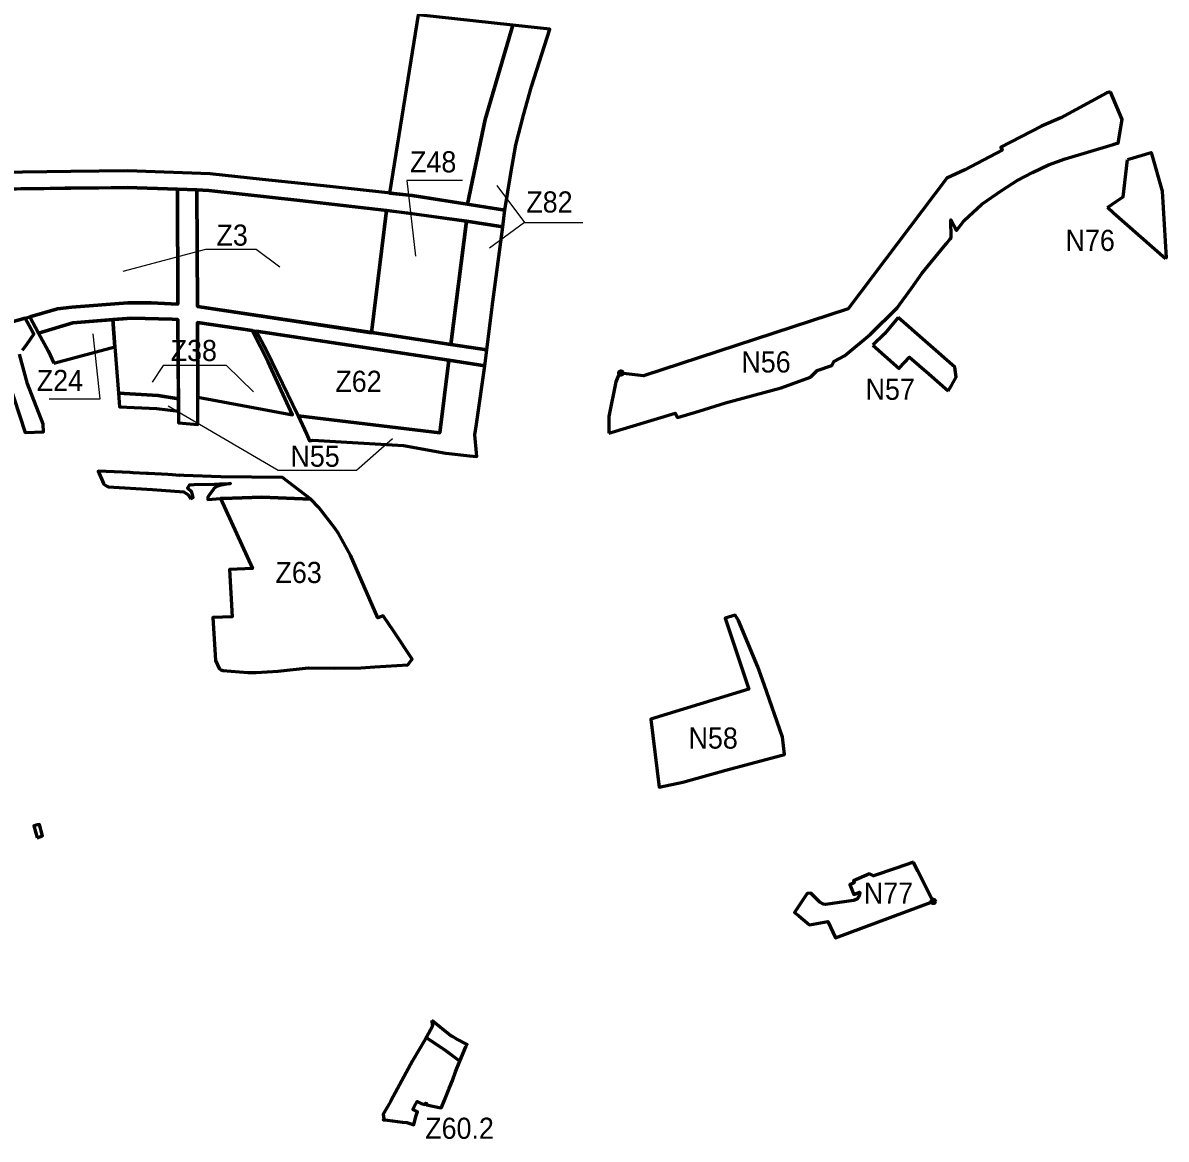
# Model space of a CAD drawing. Extents: x -650277 to -643420, y -1073980 to -1066720.
# Drawn here: x -647259 to -645961, y -1070629 to -1069362 of the extents above; entities that cross this region are included whole.
import ezdxf

# ---------------------------------------------------------------- set-up
doc = ezdxf.new("R2010")
doc.units = 0
doc.header["$LTSCALE"] = 9.6
doc.header["$PDMODE"] = 32
doc.header["$PDSIZE"] = 4.8
for name, color, linetype, lineweight in [('1', 7, 'Continuous', 60), ('13', 7, 'Continuous', 60), ('15', 7, 'Continuous', 60), ('18', 7, 'Continuous', 60), ('42', 7, 'Continuous', 60), ('48', 7, 'Continuous', 60), ('60', 7, 'Continuous', 60), ('63', 7, 'Continuous', 25), ('9', 7, 'Continuous', 60)]:
    doc.layers.add(name, color=color, linetype=linetype, lineweight=lineweight)

msp = doc.modelspace()

# ---------------------------------------------------------------- linework, layer by layer
at = {"layer": '1'}
for points in [[(-647251.002, -1069695.852), (-647219.628, -1069686.746), (-647203.374, -1069684.716), (-647139.649, -1069679.961), (-647113.255, -1069679.966), (-647082.761, -1069681.399), (-647083.356, -1069551.018), (-647140.247, -1069549.071), (-647158.572, -1069549.252), (-647211.05, -1069549.77), (-647227.623, -1069550.23), (-647327.682, -1069551.263), (-647277.71, -1069703.421)], [(-646944.168, -1069563.743), (-647047.648, -1069552.245), (-647061.304, -1069551.773), (-647060.7, -1069683.894), (-646863, -1069714), (-646846, -1069575)], [(-647223.66, -1069748.26), (-647154.33, -1069729.69), (-647156.782, -1069698.901), (-647202.181, -1069702.678), (-647240.994, -1069714.513), (-647230.16, -1069734.42)], [(-647150.138, -1069782.334), (-647105.334, -1069785.168), (-647082.271, -1069788.81), (-647082.682, -1069698.791), (-647089.456, -1069698.579), (-647135.585, -1069697.137), (-647156.782, -1069698.901), (-647154.33, -1069729.69)], [(-647060.23, -1069786.932), (-646952.56, -1069807.13), (-646980.4, -1069746.98), (-646998.56, -1069711.443), (-647060.617, -1069702.116)]]:
    msp.add_lwpolyline(points, close=True, dxfattribs=at)
at = {"layer": '13'}
msp.add_line((-646733.74, -1069471.688), (-646702.425, -1069364.771), dxfattribs=at)
msp.add_lwpolyline([(-646702.425, -1069364.771), (-646809.879, -1069353.002), (-646842.103, -1069553.182), (-646842.441, -1069555.283), (-646816.615, -1069558.064), (-646754.066, -1069567.993), (-646733.74, -1069471.688)], dxfattribs=at)
msp.add_lwpolyline([(-646842.148, -1069716.763), (-646772.906, -1069727.176), (-646755.269, -1069587.04), (-646846, -1069575), (-646862.955, -1069713.634)], close=True, dxfattribs=at)
at = {"layer": '15'}
for points in [[(-647327.682, -1069551.263), (-647204.208, -1069549.647), (-647140.247, -1069549.071), (-647083.356, -1069551.018), (-647061.304, -1069551.773), (-647047.702, -1069552.239), (-646944.167, -1069563.743), (-646822.169, -1069577.72), (-646755.269, -1069587.04), (-646714.037, -1069593.585), (-646712.34, -1069580.49), (-646711.444, -1069574.771), (-646711.442, -1069574.759), (-646816.615, -1069558.064), (-646910.029, -1069548.006), (-646986.633, -1069539.757), (-647046.325, -1069533.275), (-647140.008, -1069530.068), (-647204.293, -1069530.647), (-647341.697, -1069532.602)], [(-647346.554, -1069551.486), (-647256.034, -1069827.107), (-647235.49, -1069826.51), (-647235.62, -1069817.62), (-647253.45, -1069771.95), (-647262.46, -1069738.25)], [(-647083.356, -1069551.018), (-647082.761, -1069681.399), (-647113.255, -1069679.966), (-647139.649, -1069679.961), (-647203.374, -1069684.716), (-647219.628, -1069686.746), (-647251.002, -1069695.852), (-647240.994, -1069714.513), (-647202.181, -1069702.678), (-647135.585, -1069697.137), (-647089.456, -1069698.579), (-647082.682, -1069698.791), (-647082.206, -1069802.916)], [(-647060.617, -1069702.116), (-646998.56, -1069711.443), (-646993.771, -1069712.163), (-646775.286, -1069745.022), (-646734.48, -1069751.35), (-646732.143, -1069733.308), (-646772.906, -1069727.176), (-646842.148, -1069716.763), (-647060.7, -1069683.894), (-647061.304, -1069551.773), (-647083.356, -1069551.018)], [(-647259.11, -1069733.52), (-647253.97, -1069726.27), (-647246.42, -1069715.63), (-647249.555, -1069709.677), (-647256.061, -1069697.32), (-647277.71, -1069703.421)], [(-647082.206, -1069802.916), (-647082.145, -1069816.321), (-647060.029, -1069817.854), (-647060.23, -1069786.932), (-647060.617, -1069702.116)], [(-646931.67, -1069902.89), (-646964.111, -1069878.315), (-647034.195, -1069877.629), (-647076, -1069875.85), (-647081.25, -1069875.56), (-647081.26, -1069875.76), (-647088.94, -1069875.34), (-647088.93, -1069875.14), (-647094.24, -1069874.85), (-647116.31, -1069873.65), (-647118.77, -1069873.51), (-647133.58, -1069872.73), (-647136.94, -1069872.55), (-647173.23, -1069871.09), (-647167.14, -1069884.85)], [(-647167.14, -1069884.85), (-647166.8, -1069885.63), (-647163.55, -1069887.98), (-647162.03, -1069888.89), (-647111.76, -1069891.77)], [(-647068.2, -1069902.28), (-647065.47, -1069901.09), (-647067.02, -1069894.68), (-647071.73, -1069890.39), (-647070.87, -1069888.71), (-647069.57, -1069886.35), (-647064.32, -1069886.23), (-647041.25, -1069885.62), (-647035.6, -1069885.43), (-647023.04, -1069885), (-647035.53, -1069887.44), (-647037.79, -1069887.88), (-647041.47, -1069890.42), (-647042.75, -1069892.14), (-647046.49, -1069897.19), (-647048.8, -1069900.51), (-647048.67, -1069903.32), (-647034.51, -1069902.21)], [(-647111.76, -1069891.77), (-647075.97, -1069894.33), (-647071, -1069897.87), (-647068.2, -1069902.28)], [(-647034.51, -1069902.21), (-647032.16, -1069902.13), (-646987.56, -1069900.52), (-646931.67, -1069902.89)], [(-646794.59, -1070494.62), (-646794.53, -1070495.7), (-646793.75, -1070501.26), (-646800.6, -1070513.43), (-646800.94, -1070514.04)], [(-646755.84, -1070524.5), (-646754.52, -1070522.08), (-646765.96, -1070515.75), (-646770.95, -1070512.94), (-646773, -1070511.96), (-646794.59, -1070494.62)], [(-646800.94, -1070514.04), (-646788, -1070522.49), (-646782.63, -1070526.02)], [(-646782.63, -1070526.02), (-646779.68, -1070527.87), (-646762.71, -1070540.85), (-646755.84, -1070524.5)]]:
    msp.add_lwpolyline(points, dxfattribs=at)
msp.add_lwpolyline([(-647242.698, -1070287.238), (-647236.567, -1070285.154), (-647239.781, -1070272.031), (-647242.06, -1070272.35), (-647246.28, -1070273.733)], close=True, dxfattribs=at)
at = {"layer": '18'}
msp.add_lwpolyline([(-646785.437, -1069827.534), (-646775.286, -1069745.022), (-646993.771, -1069712.163), (-646981.92, -1069734.86), (-646946.369, -1069808.291)], close=True, dxfattribs=at)
at = {"layer": '42'}
msp.add_line((-646230.3, -1069760.5), (-646208.135, -1069779.937), dxfattribs=at)
for points in [[(-646023.96, -1069440.34), (-646028.16, -1069441.58), (-646080.35, -1069469.89), (-646102.15, -1069479.49), (-646148.5, -1069503), (-646146.8, -1069506.6), (-646189.17, -1069528.74), (-646209.9, -1069538.5), (-646321.973, -1069686.855), (-646554.262, -1069762.602), (-646579.873, -1069759.61)], [(-646017.63, -1069499.08), (-646017.63, -1069499.08), (-646015.16, -1069498.74), (-646010.65, -1069471.91), (-646023.96, -1069440.34)], [(-646491.18, -1069802.78), (-646491.18, -1069802.78), (-646460.97, -1069793.56), (-646397.74, -1069776.29), (-646364.67, -1069764.23), (-646357, -1069756.7), (-646340.48, -1069750.92), (-646337.97, -1069746.4), (-646325.92, -1069740.05), (-646296.64, -1069715.72), (-646266.27, -1069685.75), (-646250, -1069663.09), (-646238.19, -1069646.63), (-646212.43, -1069615.33), (-646210.03, -1069612.42), (-646205.9, -1069607.17), (-646205, -1069606.03), (-646205.25, -1069585.67), (-646198.82, -1069597.83), (-646190.07, -1069586.48), (-646169.9, -1069568.04), (-646146.81, -1069551.97), (-646129.87, -1069541.19), (-646112.56, -1069531.78), (-646094.39, -1069523.34), (-646075.48, -1069516.38), (-646020.75, -1069500), (-646017.63, -1069499.08)], [(-646265.02, -1069696.43), (-646280.5, -1069715.27), (-646293.76, -1069728)], [(-646208.135, -1069779.937), (-646204.6, -1069773.78), (-646199.17, -1069764.33), (-646200.67, -1069752.88), (-646265.02, -1069696.43)], [(-646293.76, -1069728), (-646263.929, -1069754.309), (-646263.36, -1069753.69), (-646252.07, -1069741.41), (-646230.3, -1069760.5)], [(-646579.873, -1069759.61), (-646581.489, -1069759.421), (-646585.51, -1069769.57), (-646593.34, -1069808.99), (-646593.34, -1069827.68)], [(-647082.271, -1069788.81), (-647105.334, -1069785.168), (-647105.334, -1069785.168), (-647150.138, -1069782.334), (-647148.9, -1069797.88), (-647107.04, -1069799.84)], [(-647107.04, -1069799.84), (-647082.206, -1069802.916), (-647082.271, -1069788.81)], [(-646593.34, -1069827.68), (-646518.19, -1069805.27), (-646515.63, -1069810.24), (-646491.18, -1069802.78)]]:
    msp.add_lwpolyline(points, dxfattribs=at)
msp.add_lwpolyline([(-646775.286, -1069745.022), (-646785.437, -1069827.534), (-646946.369, -1069808.291), (-646936.6, -1069828.47), (-646933.39, -1069836.51), (-646929.67, -1069835.68), (-646826.63, -1069841.84), (-646778.74, -1069850.44), (-646751.8, -1069853.72), (-646743.31, -1069854.26), (-646743.7, -1069850.07), (-646745.56, -1069829.84), (-646743.85, -1069817.72), (-646734.48, -1069751.35)], close=True, dxfattribs=at)
msp.add_point((-646579.873, -1069759.61), dxfattribs=at)
at = {"layer": '48'}
for points in [[(-646004.7, -1069517.16), (-645977.73, -1069509.11), (-645965.36, -1069552.99), (-645960.78, -1069628.91), (-645961.36, -1069630.05)], [(-646027.49, -1069571.79), (-646017.39, -1069564.94), (-646009.52, -1069559.6), (-646004.7, -1069517.16)], [(-645961.36, -1069630.05), (-646020.4, -1069578.04), (-646027.49, -1069571.79)]]:
    msp.add_lwpolyline(points, dxfattribs=at)
msp.add_point((-646225.15, -1070359.46), dxfattribs=at)
at = {"layer": '60'}
for points in [[(-646681.5, -1069434.17), (-646660.526, -1069369.36), (-646702.425, -1069364.771), (-646733.74, -1069471.688), (-646754.066, -1069567.993), (-646711.442, -1069574.759)], [(-646711.442, -1069574.759), (-646704.68, -1069533.06), (-646699.07, -1069500.57), (-646690.51, -1069466.97), (-646681.5, -1069434.17)]]:
    msp.add_lwpolyline(points, dxfattribs=at)
msp.add_lwpolyline([(-646755.269, -1069587.04), (-646772.906, -1069727.176), (-646732.143, -1069733.308), (-646725.82, -1069684.5), (-646714.037, -1069593.585)], close=True, dxfattribs=at)
at = {"layer": '63'}
msp.add_line((-646689.194, -1069588.733), (-646622.86, -1069588.733), dxfattribs=at)
for points in [[(-646759.573, -1069540.98), (-646822.671, -1069540.98), (-646813, -1069627)], [(-646720.743, -1069546.645), (-646689.194, -1069588.733), (-646728.832, -1069617.87)], [(-647145, -1069644), (-647051, -1069619), (-646994, -1069619), (-646967, -1069639)], [(-647229, -1069789), (-647171, -1069789), (-647179, -1069715)], [(-646997, -1069781), (-647027.656, -1069750.914), (-647099.524, -1069750.914), (-647112, -1069770)], [(-647094, -1069797), (-646969, -1069870), (-646880, -1069870), (-646839, -1069834)]]:
    msp.add_lwpolyline(points, dxfattribs=at)
at = {"layer": '9'}
for points in [[(-647032.16, -1069902.13), (-647034.51, -1069902.21), (-646998.06, -1069981.49), (-647024.05, -1069982.48), (-647021.27, -1070036.28), (-647043.25, -1070037.29), (-647040.12, -1070086.11), (-647036.03, -1070094.96), (-647034.17, -1070096.49), (-647031.73, -1070097.21), (-647003.49, -1070099.66), (-646993.92, -1070099.49), (-646968.89, -1070098.02), (-646934.63, -1070094.24), (-646904.97, -1070094.52), (-646874.9, -1070094.1), (-646859.29, -1070093.1), (-646821.89, -1070090.7), (-646817.15, -1070084.76), (-646816.9, -1070084.45), (-646837.65, -1070053.22), (-646849.79, -1070035.17), (-646855.62, -1070037.66), (-646886.85, -1069966.26), (-646900.26, -1069941.64), (-646904.72, -1069935.84), (-646922.79, -1069912.31), (-646931.67, -1069902.89), (-646987.56, -1069900.52)], [(-646247.667, -1070315.004), (-646267.3, -1070321.61), (-646293.14, -1070330.3), (-646297.4, -1070328.01), (-646315.84, -1070336.13), (-646314.84, -1070338.41), (-646319.95, -1070340.42), (-646315.46, -1070351.67), (-646308.791, -1070348.855), (-646308.59, -1070350.22), (-646309.18, -1070352.77), (-646309.99, -1070354.58), (-646311.82, -1070356.89), (-646314.6, -1070358.05), (-646315.7, -1070358.27), (-646347.49, -1070363.01), (-646349.76, -1070362.69), (-646353.81, -1070360.18), (-646364.34, -1070350.19), (-646368.4, -1070350.41), (-646382.67, -1070371.94), (-646377.86, -1070375.71), (-646365.7, -1070385.89), (-646344.93, -1070382.33), (-646336.35, -1070400.9), (-646225.15, -1070359.46), (-646242.56, -1070325.1)], [(-646802.19, -1070516.26), (-646816.42, -1070540.49), (-646828.45, -1070562.89), (-646841.16, -1070585.79), (-646844.76, -1070592.54), (-646849.72, -1070600.98), (-646848.99, -1070606.28), (-646849.59, -1070607.4), (-646844.96, -1070607.98), (-646827.88, -1070610.12), (-646822.99, -1070610.51), (-646815.05, -1070613.14), (-646812.5, -1070603.78), (-646811.5, -1070600.29), (-646810.82, -1070598.23), (-646816.11, -1070595.8), (-646814.52, -1070592.78), (-646811.06, -1070586.67), (-646806.41, -1070589), (-646802.06, -1070589.93), (-646801.73, -1070588.37), (-646800.13, -1070588.71), (-646800.47, -1070590.28), (-646784.18, -1070593.76), (-646784, -1070593.34), (-646783.59, -1070593.52), (-646779.9, -1070584.92), (-646774.91, -1070571.88), (-646771.17, -1070562.7), (-646767.63, -1070553.09), (-646762.71, -1070540.85), (-646782.63, -1070526.02), (-646788, -1070522.49), (-646800.94, -1070514.04)]]:
    msp.add_lwpolyline(points, close=True, dxfattribs=at)
for points in [[(-646417.23, -1070113.25), (-646424.17, -1070093.21), (-646446.21, -1070040.55), (-646450.22, -1070034.31), (-646461.415, -1070037.991), (-646434.503, -1070118.512), (-646545.78, -1070152.41), (-646536.47, -1070229.65), (-646509.31, -1070224.11), (-646460.8, -1070210.57)], [(-646460.8, -1070210.57), (-646393.97, -1070192.69), (-646396.51, -1070173.06), (-646417.23, -1070113.25)]]:
    msp.add_lwpolyline(points, dxfattribs=at)

# ---------------------------------------------------------------- texts
at = {"layer": '63', "width": 0.95}
for s, p in [('Z48', (-646819.248, -1069531.795)), ('Z82', (-646687.198, -1069577.402)), ('Z3', (-647039, -1069615)), ('N76', (-646075, -1069621)), ('Z38', (-647091, -1069746)), ('N56', (-646443, -1069759)), ('Z24', (-647243, -1069780)), ('Z62', (-646904, -1069781)), ('N57', (-646302, -1069790)), ('N55', (-646955, -1069866)), ('Z63', (-646972, -1069998)), ('N58', (-646503, -1070186)), ('N77', (-646304, -1070362)), ('Z60.2', (-646802, -1070629))]:
    msp.add_text(s, height=24, dxfattribs=at).set_placement(p)

doc.saveas('drawing.dxf')
